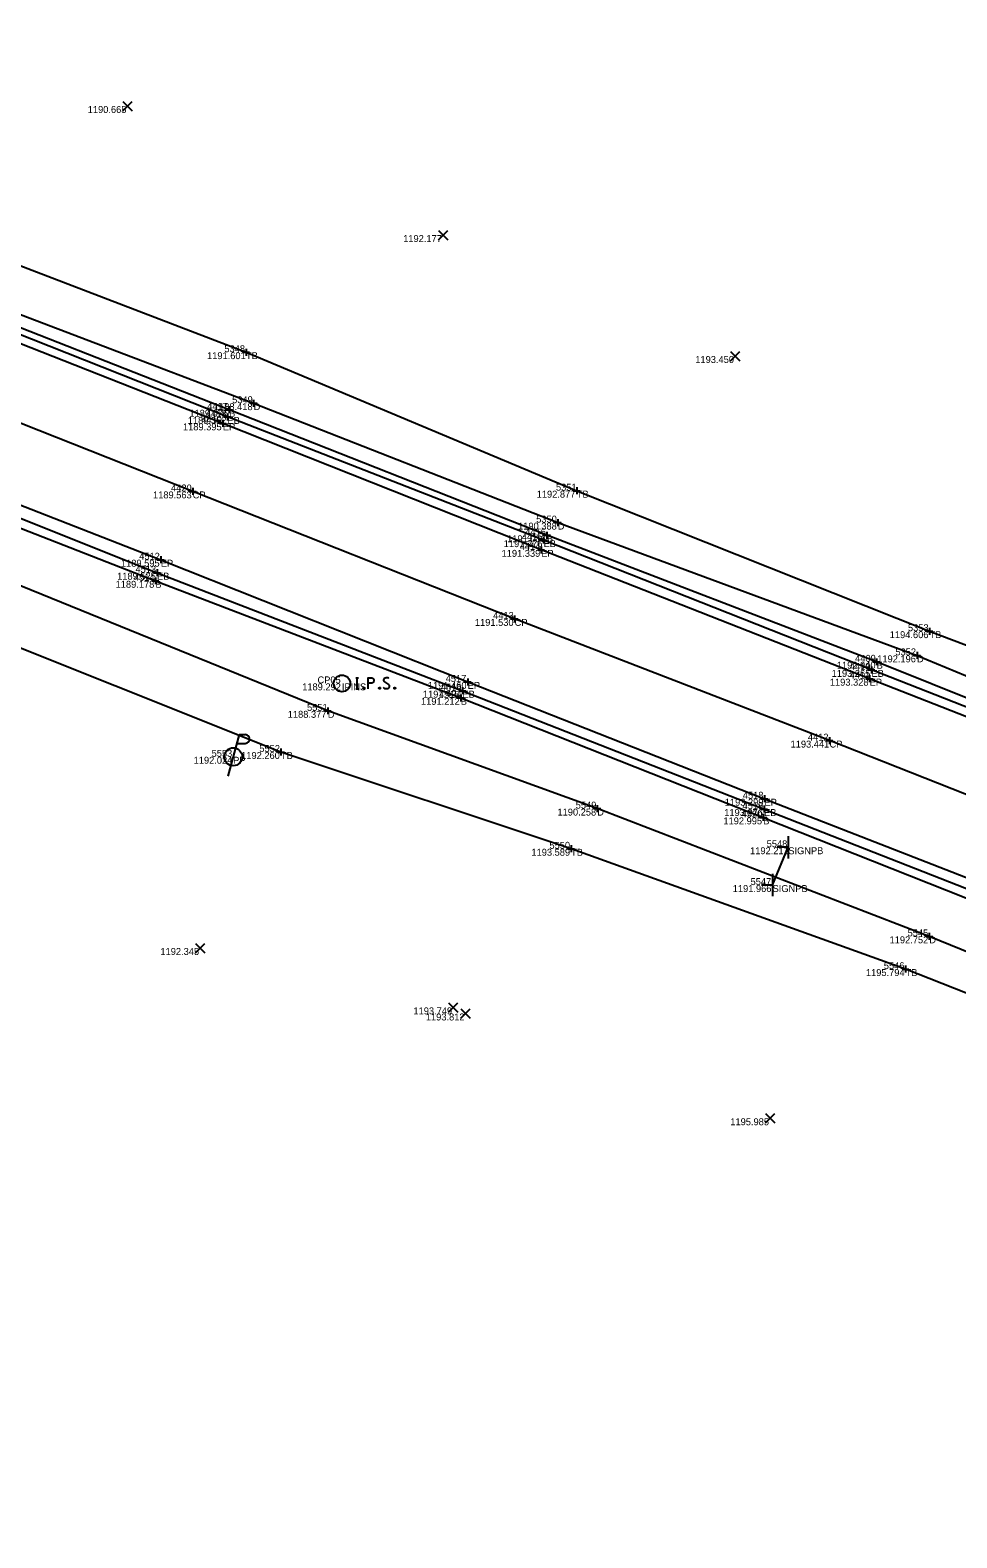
# Model space of a CAD drawing. Extents: x 2044996 to 2050343, y 455232 to 458054.
# Drawn here: x 2047198.7 to 2047332.3, y 456999.1 to 457216.4 of the extents above; entities that cross this region are included whole.
import ezdxf

# ---------------------------------------------------------------- set-up
doc = ezdxf.new("R2010")
doc.units = 0
for name, color, linetype in [('Default', 7, 'Continuous'), ('DR_X_Ditch', 7, 'Continuous'), ('DT_X_Contour_Minor', 7, 'Continuous'), ('DT_X_Contour_Text', 7, 'Continuous'), ('DT_X_Spot_Elev', 7, 'Continuous'), ('DT_X_Triangles', 7, 'Continuous'), ('DT_X_Void', 7, 'Continuous'), ('PV_X_COP', 7, 'Continuous'), ('PV_X_EOP', 7, 'Continuous'), ('PV_X_Shoulder_Aggregate', 7, 'Continuous'), ('SN_X_Public', 7, 'Continuous'), ('SV_P_Mon_Cells_Set', 7, 'Continuous'), ('SV_X_Break_Lines', 7, 'Continuous'), ('SV_X_Top_of_Bank', 7, 'Continuous'), ('UT_X_Electric_Cells', 7, 'Continuous')]:
    doc.layers.add(name, color=color, linetype=linetype)

msp = doc.modelspace()

# ---------------------------------------------------------------- linework, layer by layer
at = {"layer": 'Default'}
msp.add_lwpolyline([(2047305.73, 457093.19), (2047308, 457098.64)], dxfattribs=at)
at = {"layer": 'DR_X_Ditch'}
for points in [[(2047543.3, 457005.16), (2047510.9, 457017.43), (2047468.96, 457033.16), (2047427.45, 457048.41), (2047415.45, 457054.04), (2047370.9, 457068.47), (2047328.33, 457085.8), (2047280.45, 457104.21), (2047241.61, 457118.3), (2047187.46, 457140.33), (2047142.69, 457158.87), (2047125.5, 457162.21), (2047087.92, 457177.75), (2047044.55, 457195.18), (2046997.32, 457212.04), (2046988.97, 457212.79)], [(2047185.37, 457179.96), (2047230.91, 457162.64), (2047274.77, 457145.43), (2047326.56, 457126.3), (2047357.24, 457113.6), (2047397.5, 457098.28), (2047439.04, 457082.1), (2047486.14, 457064.57), (2047529.75, 457047.81), (2047563.13, 457037.52)]]:
    msp.add_lwpolyline(points, dxfattribs=at)
at = {"layer": 'DT_X_Spot_Elev'}
for p, q in [((2047212.07, 457204.8), (2047213.4, 457206.14)), ((2047212.07, 457206.14), (2047213.4, 457204.8)), ((2047257.58, 457186.2), (2047258.92, 457187.53)), ((2047257.58, 457187.53), (2047258.92, 457186.2)), ((2047299.66, 457168.77), (2047300.99, 457170.1)), ((2047299.66, 457170.1), (2047300.99, 457168.77)), ((2047222.55, 457083.45), (2047223.88, 457084.78)), ((2047222.55, 457084.78), (2047223.88, 457083.45)), ((2047258.99, 457074.89), (2047260.33, 457076.23)), ((2047258.99, 457076.23), (2047260.33, 457074.89)), ((2047260.8, 457074.01), (2047262.13, 457075.34)), ((2047260.8, 457075.34), (2047262.13, 457074.01)), ((2047304.71, 457058.91), (2047306.05, 457060.25)), ((2047304.71, 457060.25), (2047306.05, 457058.91))]:
    msp.add_line(p, q, dxfattribs=at)
at = {"layer": 'DT_X_Void'}
for p, q in [((2047229.31, 457169.99), (2047230.31, 457169.99)), ((2047229.81, 457170.49), (2047229.81, 457169.49)), ((2047229.81, 457169.99), (2047229.81, 457169.99)), ((2047230.41, 457162.64), (2047231.41, 457162.64)), ((2047230.91, 457163.14), (2047230.91, 457162.14)), ((2047230.91, 457162.64), (2047230.91, 457162.64)), ((2047226.47, 457160.23), (2047226.47, 457159.23)), ((2047226.64, 457160.66), (2047227.64, 457160.66)), ((2047226.87, 457161.69), (2047227.87, 457161.69)), ((2047227.14, 457161.16), (2047227.14, 457160.16)), ((2047227.14, 457160.66), (2047227.14, 457160.66)), ((2047227.37, 457162.19), (2047227.37, 457161.19)), ((2047227.37, 457161.69), (2047227.37, 457161.69)), ((2047225.97, 457159.73), (2047226.97, 457159.73)), ((2047226.47, 457159.73), (2047226.47, 457159.73)), ((2047221.62, 457149.92), (2047222.62, 457149.92)), ((2047222.12, 457150.42), (2047222.12, 457149.42)), ((2047222.12, 457149.92), (2047222.12, 457149.92)), ((2047277, 457150.03), (2047278, 457150.03)), ((2047277.5, 457150.53), (2047277.5, 457149.53)), ((2047277.5, 457150.03), (2047277.5, 457150.03)), ((2047274.27, 457145.43), (2047275.27, 457145.43)), ((2047274.77, 457145.93), (2047274.77, 457144.93)), ((2047274.77, 457145.43), (2047274.77, 457145.43)), ((2047272.21, 457142.9), (2047273.21, 457142.9)), ((2047272.69, 457143.6), (2047273.69, 457143.6)), ((2047272.71, 457143.4), (2047272.71, 457142.4)), ((2047272.71, 457142.9), (2047272.71, 457142.9)), ((2047273.19, 457144.1), (2047273.19, 457143.1)), ((2047273.19, 457143.6), (2047273.19, 457143.6)), ((2047271.87, 457141.5), (2047272.87, 457141.5)), ((2047272.37, 457142), (2047272.37, 457141)), ((2047272.37, 457141.5), (2047272.37, 457141.5)), ((2047216.98, 457138.71), (2047216.98, 457137.71)), ((2047217.02, 457140.08), (2047218.02, 457140.08)), ((2047217.52, 457140.58), (2047217.52, 457139.58)), ((2047217.52, 457140.08), (2047217.52, 457140.08)), ((2047216.25, 457137.04), (2047217.25, 457137.04)), ((2047216.48, 457138.21), (2047217.48, 457138.21)), ((2047216.75, 457137.54), (2047216.75, 457136.54)), ((2047216.75, 457137.04), (2047216.75, 457137.04)), ((2047216.98, 457138.21), (2047216.98, 457138.21)), ((2047268.54, 457132.05), (2047268.54, 457131.05)), ((2047268.04, 457131.55), (2047269.04, 457131.55)), ((2047268.54, 457131.55), (2047268.54, 457131.55)), ((2047328.36, 457130.28), (2047328.36, 457129.28)), ((2047327.86, 457129.78), (2047328.86, 457129.78)), ((2047328.36, 457129.78), (2047328.36, 457129.78)), ((2047320.74, 457125.87), (2047320.74, 457124.87)), ((2047326.06, 457126.3), (2047327.06, 457126.3)), ((2047326.56, 457126.8), (2047326.56, 457125.8)), ((2047326.56, 457126.3), (2047326.56, 457126.3)), ((2047319.49, 457124.2), (2047320.49, 457124.2)), ((2047319.73, 457123.43), (2047319.73, 457122.43)), ((2047319.99, 457124.7), (2047319.99, 457123.7)), ((2047319.99, 457124.2), (2047319.99, 457124.2)), ((2047320.24, 457125.37), (2047321.24, 457125.37)), ((2047320.74, 457125.37), (2047320.74, 457125.37)), ((2047260.52, 457121.2), (2047261.52, 457121.2)), ((2047261.02, 457121.7), (2047261.02, 457120.7)), ((2047261.02, 457121.2), (2047261.02, 457121.2)), ((2047261.27, 457122.46), (2047262.27, 457122.46)), ((2047261.77, 457122.96), (2047261.77, 457121.96)), ((2047261.77, 457122.46), (2047261.77, 457122.46)), ((2047319.23, 457122.93), (2047320.23, 457122.93)), ((2047319.73, 457122.93), (2047319.73, 457122.93)), ((2047260.27, 457120.17), (2047261.27, 457120.17)), ((2047260.77, 457120.67), (2047260.77, 457119.67)), ((2047260.77, 457120.17), (2047260.77, 457120.17)), ((2047241.11, 457118.3), (2047242.11, 457118.3)), ((2047241.61, 457118.8), (2047241.61, 457117.8)), ((2047241.61, 457118.3), (2047241.61, 457118.3)), ((2047234.84, 457112.87), (2047234.84, 457111.87)), ((2047313.44, 457114.01), (2047314.44, 457114.01)), ((2047313.94, 457114.51), (2047313.94, 457113.51)), ((2047313.94, 457114.01), (2047313.94, 457114.01)), ((2047234.34, 457112.37), (2047235.34, 457112.37)), ((2047234.84, 457112.37), (2047234.84, 457112.37)), ((2047304.56, 457106.13), (2047304.56, 457105.13)), ((2047279.95, 457104.21), (2047280.95, 457104.21)), ((2047280.45, 457104.71), (2047280.45, 457103.71)), ((2047280.45, 457104.21), (2047280.45, 457104.21)), ((2047304, 457104.14), (2047305, 457104.14)), ((2047304.06, 457105.63), (2047305.06, 457105.63)), ((2047304.5, 457104.64), (2047304.5, 457103.64)), ((2047304.5, 457104.14), (2047304.5, 457104.14)), ((2047304.56, 457105.63), (2047304.56, 457105.63)), ((2047303.88, 457102.94), (2047304.88, 457102.94)), ((2047304.38, 457103.44), (2047304.38, 457102.44)), ((2047304.38, 457102.94), (2047304.38, 457102.94)), ((2047276.18, 457098.42), (2047277.18, 457098.42)), ((2047276.68, 457098.92), (2047276.68, 457097.92)), ((2047276.68, 457098.42), (2047276.68, 457098.42)), ((2047327.83, 457085.8), (2047328.83, 457085.8)), ((2047328.33, 457086.3), (2047328.33, 457085.3)), ((2047328.33, 457085.8), (2047328.33, 457085.8)), ((2047324.4, 457081.08), (2047325.4, 457081.08)), ((2047324.9, 457081.58), (2047324.9, 457080.58)), ((2047324.9, 457081.08), (2047324.9, 457081.08))]:
    msp.add_line(p, q, dxfattribs=at)
at = {"layer": 'PV_X_COP'}
msp.add_lwpolyline([(2047612.39, 456999.11), (2047580.09, 457011.53), (2047538.37, 457027.53), (2047496.01, 457043.83), (2047451.82, 457060.1), (2047409.77, 457076.51), (2047364.77, 457093.97), (2047313.94, 457114.01), (2047268.54, 457131.55), (2047222.12, 457149.92), (2047177.7, 457167.48), (2047132.78, 457184.84), (2047088.94, 457201.35), (2047045.02, 457217.22), (2047000.47, 457231.97), (2046961.14, 457242.7), (2046914.32, 457253.6), (2046869.82, 457261.81), (2046824.05, 457268.96), (2046778.68, 457274.62), (2046733.92, 457279.83), (2046684.61, 457284.92), (2046649.61, 457288.12)], dxfattribs=at)
at = {"layer": 'PV_X_EOP'}
for p, q in [((2047226.47, 457159.73), (2047182.8, 457176.87)), ((2047272.37, 457141.5), (2047226.47, 457159.73)), ((2047173.78, 457157.15), (2047217.52, 457140.08)), ((2047319.73, 457122.93), (2047272.37, 457141.5)), ((2047217.52, 457140.08), (2047261.77, 457122.46)), ((2047261.77, 457122.46), (2047304.56, 457105.63)), ((2047368.13, 457103.89), (2047319.73, 457122.93)), ((2047304.56, 457105.63), (2047350.6, 457087.64))]:
    msp.add_line(p, q, dxfattribs=at)
at = {"layer": 'PV_X_Shoulder_Aggregate'}
for p, q in [((2047227.14, 457160.66), (2047183.36, 457178.03)), ((2047272.71, 457142.9), (2047227.14, 457160.66)), ((2047172.79, 457155.85), (2047216.98, 457138.21)), ((2047319.99, 457124.2), (2047272.71, 457142.9)), ((2047216.98, 457138.21), (2047261.02, 457121.2)), ((2047368.53, 457105.21), (2047319.99, 457124.2)), ((2047261.02, 457121.2), (2047304.5, 457104.14)), ((2047304.5, 457104.14), (2047349.8, 457086.36))]:
    msp.add_line(p, q, dxfattribs=at)
at = {"layer": 'SN_X_Public'}
for p, q in [((2047308, 457100.24), (2047308, 457097.04)), ((2047308, 457098.64), (2047306.4, 457098.64)), ((2047305.73, 457093.19), (2047304.13, 457093.19)), ((2047305.73, 457094.79), (2047305.73, 457091.59))]:
    msp.add_line(p, q, dxfattribs=at)
at = {"layer": 'SV_P_Mon_Cells_Set'}
for points in [[(2047245.66, 457123.07), (2047246.01, 457123.07)], [(2047245.66, 457121.47), (2047246.01, 457121.47)], [(2047245.83, 457121.47), (2047245.83, 457123.07)], [(2047246.79, 457121.68), (2047246.85, 457121.68), (2047246.88, 457121.66), (2047246.91, 457121.61), (2047246.91, 457121.54), (2047246.88, 457121.49), (2047246.85, 457121.47), (2047246.79, 457121.47), (2047246.76, 457121.49), (2047246.72, 457121.54), (2047246.72, 457121.61), (2047246.76, 457121.66), (2047246.79, 457121.68)], [(2047247.4, 457121.47), (2047247.4, 457123.07), (2047247.93, 457123.07), (2047247.98, 457123.05), (2047248.06, 457123.03), (2047248.09, 457123), (2047248.12, 457122.98), (2047248.17, 457122.92), (2047248.2, 457122.85), (2047248.22, 457122.75), (2047248.22, 457122.6), (2047248.21, 457122.55), (2047248.19, 457122.47), (2047248.15, 457122.39), (2047248.1, 457122.35), (2047248.07, 457122.32), (2047248.01, 457122.3), (2047247.93, 457122.29), (2047247.4, 457122.29)], [(2047249.04, 457121.68), (2047249.09, 457121.68), (2047249.13, 457121.66), (2047249.16, 457121.61), (2047249.16, 457121.54), (2047249.13, 457121.49), (2047249.09, 457121.47), (2047249.04, 457121.47), (2047249.01, 457121.49), (2047248.97, 457121.54), (2047248.97, 457121.61), (2047249.01, 457121.66), (2047249.04, 457121.68)], [(2047250.41, 457122.95), (2047250.38, 457122.98), (2047250.35, 457123), (2047250.25, 457123.04), (2047250.13, 457123.07), (2047250.04, 457123.07), (2047250.01, 457123.07), (2047249.87, 457123.03), (2047249.74, 457122.95), (2047249.67, 457122.85), (2047249.65, 457122.75), (2047249.65, 457122.68), (2047249.67, 457122.57), (2047249.76, 457122.49), (2047250.36, 457122.11), (2047250.42, 457122.06), (2047250.44, 457122.01), (2047250.46, 457121.93), (2047250.46, 457121.86), (2047250.45, 457121.78), (2047250.44, 457121.73), (2047250.42, 457121.67), (2047250.39, 457121.62), (2047250.37, 457121.58), (2047250.34, 457121.54), (2047250.31, 457121.52), (2047250.26, 457121.49), (2047250.23, 457121.48), (2047250.13, 457121.47), (2047249.98, 457121.47), (2047249.88, 457121.49), (2047249.73, 457121.58), (2047249.65, 457121.66)], [(2047251.22, 457121.68), (2047251.28, 457121.68), (2047251.31, 457121.66), (2047251.34, 457121.61), (2047251.34, 457121.54), (2047251.31, 457121.49), (2047251.28, 457121.47), (2047251.22, 457121.47), (2047251.19, 457121.49), (2047251.16, 457121.54), (2047251.16, 457121.61), (2047251.19, 457121.66), (2047251.22, 457121.68)]]:
    msp.add_lwpolyline(points, dxfattribs=at)
msp.add_circle((2047243.64, 457122.26), 1.2, dxfattribs=at)
at = {"layer": 'SV_X_Break_Lines'}
for points in [[(2047609.61, 457393.11), (2047610.32, 457343.26), (2047611.06, 457296.5), (2047612.48, 457248.74), (2047612.89, 457199.62), (2047614.53, 457148.61), (2047615.46, 457101.16), (2047615.94, 457053.96), (2047615.5, 457044.29), (2047611.53, 457035.42), (2047600.94, 457028.5), (2047592.5, 457026.1), (2047589.23, 457026.31), (2047543.28, 457040.88), (2047500.59, 457056.09), (2047456.76, 457072.2), (2047414.82, 457088.31), (2047369.13, 457105.97), (2047320.74, 457125.37), (2047273.19, 457143.6), (2047227.37, 457161.69), (2047183.55, 457178.86)], [(2046644.99, 457274.79), (2046684.79, 457271.32), (2046731.45, 457265.98), (2046776.36, 457261.92), (2046820.97, 457255.96), (2046865.17, 457248.93), (2046910.62, 457240.57), (2046953.49, 457230.48), (2046996.08, 457218.34), (2047041.05, 457204.36), (2047086.23, 457188.11), (2047130.38, 457171.33), (2047171.93, 457154.51), (2047216.75, 457137.04), (2047260.77, 457120.17), (2047304.38, 457102.94), (2047349.36, 457085.13), (2047391.24, 457069.28), (2047438.05, 457051.14), (2047480.2, 457035.91), (2047522.53, 457019.68), (2047543.14, 457011.06)]]:
    msp.add_lwpolyline(points, dxfattribs=at)
at = {"layer": 'SV_X_Top_of_Bank'}
for points in [[(2046651.93, 457311.46), (2046700.58, 457305.72), (2046746.85, 457300.37), (2046773.13, 457296.21), (2046810.21, 457291.65), (2046866.31, 457282.87), (2046913.13, 457276.05), (2046946.87, 457270.5), (2046956.84, 457268.66), (2047005.28, 457255.73), (2047019.97, 457251.51), (2047064.03, 457231.46), (2047107.63, 457215.29), (2047146.99, 457200.96), (2047188.63, 457185.75), (2047229.81, 457169.99), (2047277.5, 457150.03), (2047328.36, 457129.78), (2047359.21, 457118.11), (2047442.14, 457085.97), (2047488.03, 457067.35), (2047530.83, 457050.42), (2047563.67, 457038.95)], [(2047542.15, 457001.74), (2047509.52, 457012.3), (2047466.73, 457029.21), (2047424.59, 457044.27), (2047411.67, 457048.03), (2047368.41, 457063.9), (2047324.9, 457081.08), (2047276.68, 457098.42), (2047234.84, 457112.37), (2047186.92, 457131.46), (2047138.32, 457152.85), (2047124.48, 457159.14), (2047084.84, 457174.36), (2047041.82, 457189.99), (2046999.84, 457207.19), (2046987.02, 457211.13)]]:
    msp.add_lwpolyline(points, dxfattribs=at)
at = {"layer": 'UT_X_Electric_Cells'}
for p, q in [((2047228.82, 457114.88), (2047227.21, 457108.88)), ((2047228.82, 457114.88), (2047229.67, 457114.88)), ((2047228.47, 457113.6), (2047229.67, 457113.6))]:
    msp.add_line(p, q, dxfattribs=at)
msp.add_circle((2047227.96, 457111.68), 1.3, dxfattribs=at)
msp.add_arc((2047229.68, 457114.24), 0.638, 268.8767, 91.1233, dxfattribs=at)

# ---------------------------------------------------------------- texts
at = {"layer": 'DT_X_Contour_Minor'}
for s, p in [('1190.665', (2047206.99, 457204.47)), ('1192.177', (2047252.47, 457185.87)), ('1191.601', (2047224.19, 457168.99)), ('1193.450', (2047294.59, 457168.44)), ('1188.418', (2047225.18, 457161.64)), ('1189.352', (2047221.41, 457159.66)), ('1189.076', (2047221.64, 457160.69)), ('1189.395', (2047220.72, 457158.73)), ('1189.563', (2047216.4, 457148.92)), ('1192.877', (2047271.72, 457149.03)), ('1190.388', (2047269.04, 457144.43)), ('1191.276', (2047266.97, 457141.9)), ('1191.016', (2047267.46, 457142.6)), ('1191.339', (2047266.66, 457140.5)), ('1189.595', (2047211.78, 457139.08)), ('1189.178', (2047211.01, 457136.04)), ('1189.525', (2047211.23, 457137.21)), ('1191.530', (2047262.81, 457130.55)), ('1194.606', (2047322.63, 457128.78)), ('1192.196', (2047320.82, 457125.3)), ('1193.265', (2047314.25, 457123.2)), ('1192.940', (2047315, 457124.37)), ('1189.292', (2047237.91, 457121.26)), ('1191.424', (2047255.31, 457120.2)), ('1191.460', (2047256.03, 457121.46)), ('1193.328', (2047313.99, 457121.93)), ('1191.212', (2047255.04, 457119.17)), ('1188.377', (2047235.83, 457117.3)), ('1193.441', (2047308.33, 457113.01)), ('1192.024', (2047222.26, 457110.68)), ('1192.260', (2047229.11, 457111.37)), ('1190.258', (2047274.72, 457103.21)), ('1193.276', (2047298.76, 457103.14)), ('1193.299', (2047298.84, 457104.63)), ('1192.995', (2047298.64, 457101.94)), ('1193.589', (2047270.96, 457097.42)), ('1192.211', (2047302.49, 457097.64)), ('1191.966', (2047299.99, 457092.19)), ('1192.752', (2047322.6, 457084.8)), ('1192.345', (2047217.47, 457083.12)), ('1195.794', (2047319.19, 457080.08)), ('1193.749', (2047253.95, 457074.56)), ('1193.812', (2047255.74, 457073.68)), ('1195.985', (2047299.64, 457058.58))]:
    msp.add_text(s, height=1, dxfattribs=at).set_placement(p)
at = {"layer": 'DT_X_Contour_Text'}
for s, p in [('TB', (2047229.81, 457168.99)), ('D', (2047230.91, 457161.64)), ('EB', (2047227.14, 457159.66)), ('B', (2047227.37, 457160.69)), ('EP', (2047226.47, 457158.73)), ('CP', (2047222.12, 457148.92)), ('TB', (2047277.5, 457149.03)), ('D', (2047274.77, 457144.43)), ('EB', (2047272.71, 457141.9)), ('B', (2047273.19, 457142.6)), ('EP', (2047272.37, 457140.5)), ('EP', (2047217.52, 457139.08)), ('B', (2047216.75, 457136.04)), ('EB', (2047216.98, 457137.21)), ('CP', (2047268.54, 457130.55)), ('TB', (2047328.36, 457128.78)), ('D', (2047326.56, 457125.3)), ('EB', (2047319.99, 457123.2)), ('B', (2047320.74, 457124.37)), ('IPINS', (2047243.64, 457121.26)), ('EB', (2047261.02, 457120.2)), ('EP', (2047261.77, 457121.46)), ('EP', (2047319.73, 457121.93)), ('B', (2047260.77, 457119.17)), ('D', (2047241.61, 457117.3)), ('CP', (2047313.94, 457113.01)), ('PP', (2047227.96, 457110.68)), ('TB', (2047234.84, 457111.37)), ('D', (2047280.45, 457103.21)), ('EB', (2047304.5, 457103.14)), ('EP', (2047304.56, 457104.63)), ('B', (2047304.38, 457101.94)), ('TB', (2047276.68, 457097.42)), ('SIGNPB', (2047308, 457097.64)), ('SIGNPB', (2047305.73, 457092.19)), ('D', (2047328.33, 457084.8)), ('TB', (2047324.9, 457080.08))]:
    msp.add_text(s, height=1, dxfattribs=at).set_placement(p)
at = {"layer": 'DT_X_Triangles'}
for s, p in [('5348', (2047226.69, 457169.99)), ('4417', (2047224.21, 457161.69)), ('5349', (2047227.81, 457162.64)), ('4419', (2047223.37, 457159.73)), ('4418', (2047224.02, 457160.66)), ('4420', (2047219, 457149.92)), ('5351', (2047274.5, 457150.03)), ('5350', (2047271.65, 457145.43)), ('4415', (2047269.58, 457142.9)), ('4416', (2047270.07, 457143.6)), ('4512', (2047214.41, 457140.08)), ('4414', (2047269.28, 457141.5)), ('4513', (2047213.87, 457138.21)), ('4514', (2047213.66, 457137.04)), ('4413', (2047265.44, 457131.55)), ('5353', (2047325.25, 457129.78)), ('4409', (2047317.64, 457125.37)), ('5352', (2047323.44, 457126.3)), ('CP05', (2047240.12, 457122.26)), ('4517', (2047258.6, 457122.46)), ('4411', (2047316.83, 457122.93)), ('4410', (2047316.87, 457124.2)), ('4515', (2047257.64, 457120.17)), ('4516', (2047257.9, 457121.2)), ('5551', (2047238.61, 457118.3)), ('4412', (2047310.82, 457114.01)), ('5553', (2047224.85, 457111.68)), ('5552', (2047231.73, 457112.37)), ('4518', (2047301.44, 457105.63)), ('5549', (2047277.35, 457104.21)), ('4520', (2047301.26, 457102.94)), ('4519', (2047301.4, 457104.14)), ('5550', (2047273.56, 457098.42)), ('5548', (2047304.88, 457098.64)), ('5547', (2047302.56, 457093.19)), ('5545', (2047325.2, 457085.8)), ('5546', (2047321.77, 457081.08))]:
    msp.add_text(s, height=1, dxfattribs=at).set_placement(p)

doc.saveas('drawing.dxf')
